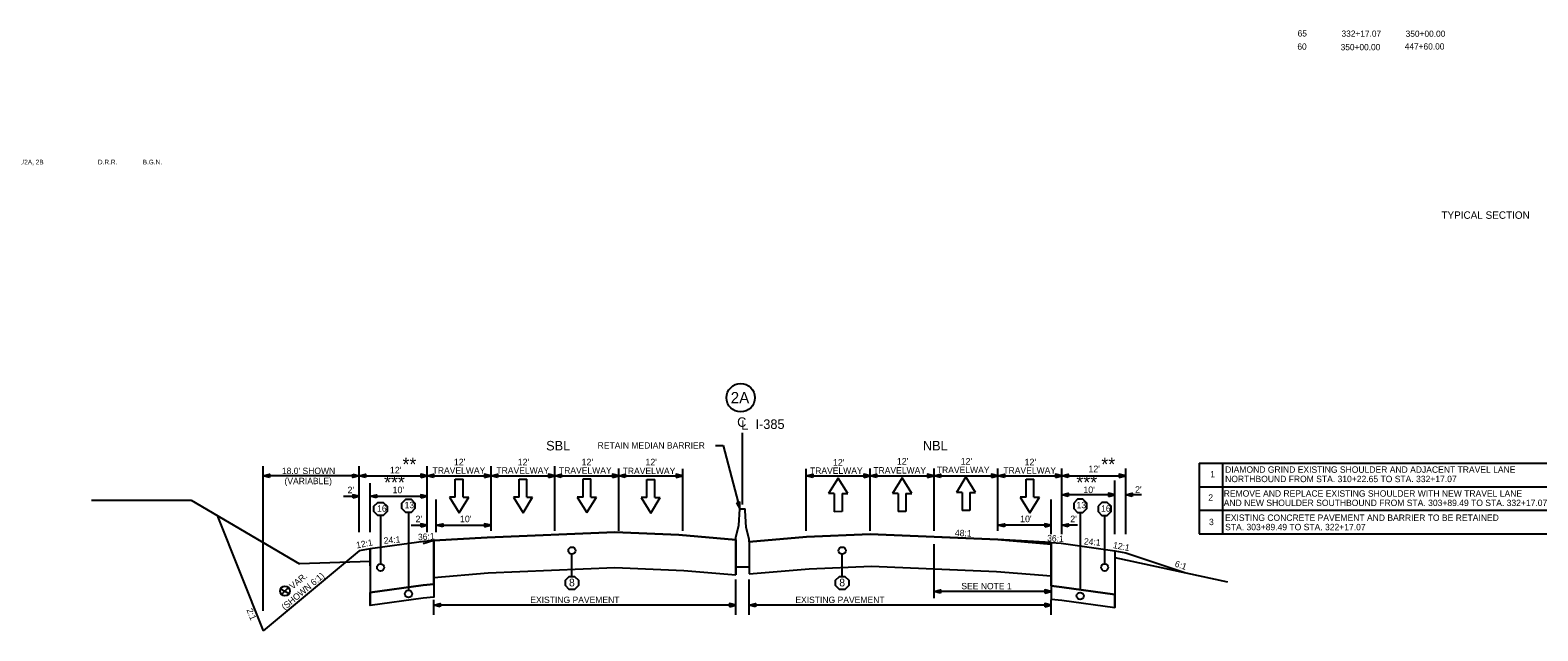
# Model space of a CAD drawing. Extents: x 4832 to 5477, y 4935 to 5220.
# Drawn here: x 5049.2 to 5332.6, y 4935 to 5047.9 of the extents above; entities that cross this region are included whole.
import ezdxf

# ---------------------------------------------------------------- set-up
doc = ezdxf.new("R2010")
doc.units = 0
for name, color, linetype in [('CLS_Clear_Zone', 7, 'Continuous'), ('Level 10', 7, 'Continuous'), ('Level 25', 7, 'Continuous'), ('Level 55', 7, 'Continuous'), ('RD_QTY_Milling', 7, 'Continuous'), ('RD_QTY_Surf_Course', 7, 'Continuous'), ('RD_SHT_TX', 7, 'Continuous'), ('RD_SHT_Typical', 7, 'Continuous'), ('RD_TX_Misc1', 7, 'Continuous'), ('RD_TX_RoadID', 7, 'Continuous'), ('RD_TX_TypSect', 7, 'Continuous'), ('RD_XS_ExPaveRet', 7, 'Continuous'), ('RD_XS_PaveShd', 7, 'Continuous'), ('TERMINATOR', 7, 'Continuous'), ('typical2', 7, 'Continuous'), ('typical_on', 7, 'Continuous')]:
    doc.layers.add(name, color=color, linetype=linetype)

# ---------------------------------------------------------------- blocks, each defined once
blk = doc.blocks.new('AH')
at = {"layer": 'TERMINATOR'}
blk.add_lwpolyline([(-6, 1.5), (0, 0), (-6, -1.5)], close=True, dxfattribs=at)

msp = doc.modelspace()

# ---------------------------------------------------------------- linework, layer by layer
at = {"layer": 'CLS_Clear_Zone'}
for p, q in [((5113.11, 4942.23), (5113.11, 4939.76)), ((5125.11, 4943.81), (5125.11, 4941.34)), ((5241.11, 4943.45), (5241.11, 4940.98)), ((5253.11, 4941.86), (5253.11, 4939.39))]:
    msp.add_line(p, q, dxfattribs=at)
at = {"layer": 'Level 10'}
for p, q in [((5219.11, 4952.68), (5231.11, 4952.18)), ((5231.11, 4952.18), (5241.11, 4951.62))]:
    msp.add_line(p, q, dxfattribs=at)
at = {"layer": 'Level 25'}
msp.add_circle((5182.77, 4978.84), 2.67, dxfattribs=at)
at = {"layer": 'Level 55'}
for p, q in [((5060.74, 4959.57), (5079.47, 4959.57)), ((5079.47, 4959.57), (5099.87, 4947.63)), ((5182.44, 4954.81), (5182.61, 4957.98)), ((5182.61, 4957.98), (5183.11, 4957.98)), ((5183.11, 4957.98), (5183.61, 4957.98)), ((5183.61, 4957.61), (5183.61, 4957.98)), ((5183.78, 4954.45), (5183.61, 4957.61)), ((5181.86, 4952.65), (5182.44, 4954.81)), ((5184.36, 4952.28), (5183.78, 4954.45)), ((5125.11, 4951.99), (5123.11, 4951.38)), ((5181.86, 4952.15), (5181.86, 4952.65)), ((5184.36, 4951.78), (5184.36, 4952.28)), ((5113.11, 4948.04), (5099.87, 4947.63)), ((5253.11, 4948.83), (5274.27, 4944.22)), ((5181.86, 4947.06), (5184.36, 4947.06))]:
    msp.add_line(p, q, dxfattribs=at)
at = {"layer": 'RD_QTY_Milling'}
for points in [[(5113.11, 4942.23), (5123.11, 4943.63), (5125.11, 4943.81), (5125.11, 4941.34), (5123.11, 4941.16), (5113.11, 4939.76)], [(5253.11, 4941.86), (5243.11, 4943.26), (5241.11, 4943.45), (5241.11, 4940.98), (5243.11, 4940.79), (5253.11, 4939.39)]]:
    msp.add_lwpolyline(points, close=True, dxfattribs=at)
at = {"layer": 'RD_SHT_Typical'}
for p, q in [((5084.36, 4956.71), (5093.04, 4935.02)), ((5125.11, 4951.99), (5123.21, 4951.84)), ((5125.11, 4951.99), (5125.11, 4943.81)), ((5241.11, 4951.62), (5243.01, 4951.48)), ((5241.11, 4951.62), (5241.11, 4943.42)), ((5111.05, 4950.03), (5093.04, 4935.02)), ((5113.11, 4948.82), (5113.11, 4950.43)), ((5113.11, 4947.21), (5113.11, 4948.82)), ((5113.11, 4947.21), (5113.11, 4942.23)), ((5123.11, 4943.63), (5113.11, 4942.23)), ((5125.11, 4943.81), (5123.11, 4943.63)), ((5241.11, 4943.45), (5243.11, 4943.26)), ((5241.11, 4943.45), (5243.11, 4943.26)), ((5243.11, 4943.26), (5253.11, 4941.86)), ((5243.11, 4943.26), (5253.11, 4941.86)), ((5123.11, 4941.16), (5113.11, 4939.76)), ((5125.11, 4941.34), (5123.11, 4941.16)), ((5241.11, 4940.98), (5243.11, 4940.79)), ((5243.11, 4940.79), (5253.11, 4939.39))]:
    msp.add_line(p, q, dxfattribs=at)
at = {"layer": 'RD_TX_Misc1'}
for p, q in [((5129.13, 4963.55), (5130.58, 4963.56)), ((5129.13, 4960.15), (5129.13, 4963.55)), ((5130.58, 4960.15), (5130.58, 4963.56)), ((5141.13, 4963.55), (5142.59, 4963.56)), ((5141.13, 4960.15), (5141.13, 4963.55)), ((5142.59, 4960.15), (5142.59, 4963.56)), ((5153.14, 4963.57), (5154.6, 4963.58)), ((5153.14, 4960.16), (5153.14, 4963.57)), ((5154.6, 4960.17), (5154.6, 4963.58)), ((5165.14, 4963.46), (5166.6, 4963.47)), ((5165.14, 4960.06), (5165.14, 4963.46)), ((5166.6, 4960.07), (5166.6, 4963.47)), ((5201.08, 4963.75), (5199.3, 4960.82)), ((5202.91, 4960.83), (5201.08, 4963.75)), ((5213.09, 4963.76), (5211.3, 4960.83)), ((5214.91, 4960.84), (5213.09, 4963.76)), ((5225.09, 4963.94), (5223.31, 4961.02)), ((5226.92, 4961.03), (5225.09, 4963.94)), ((5236.41, 4963.55), (5237.87, 4963.56)), ((5236.41, 4960.15), (5236.41, 4963.55)), ((5237.87, 4960.15), (5237.87, 4963.56)), ((5129.13, 4960.15), (5128.03, 4960.14)), ((5128.03, 4960.14), (5129.86, 4957.23)), ((5129.86, 4957.23), (5131.64, 4960.15)), ((5130.58, 4960.15), (5131.64, 4960.15)), ((5141.13, 4960.15), (5140.04, 4960.14)), ((5140.04, 4960.14), (5141.86, 4957.23)), ((5141.86, 4957.23), (5143.65, 4960.15)), ((5142.59, 4960.15), (5143.65, 4960.15)), ((5153.14, 4960.16), (5152.04, 4960.16)), ((5152.04, 4960.16), (5153.87, 4957.25)), ((5153.87, 4957.25), (5155.65, 4960.17)), ((5154.6, 4960.17), (5155.65, 4960.17)), ((5165.14, 4960.06), (5164.05, 4960.06)), ((5164.05, 4960.06), (5165.87, 4957.14)), ((5165.87, 4957.14), (5167.66, 4960.07)), ((5166.6, 4960.07), (5167.66, 4960.07)), ((5200.35, 4960.82), (5199.3, 4960.82)), ((5200.35, 4960.82), (5200.35, 4957.42)), ((5201.81, 4960.83), (5202.91, 4960.83)), ((5201.81, 4960.83), (5201.81, 4957.43)), ((5212.36, 4960.83), (5211.3, 4960.83)), ((5212.36, 4960.83), (5212.36, 4957.43)), ((5213.82, 4960.84), (5214.91, 4960.84)), ((5213.82, 4960.84), (5213.82, 4957.44)), ((5224.37, 4961.02), (5223.31, 4961.02)), ((5224.37, 4961.02), (5224.37, 4957.61)), ((5225.82, 4961.02), (5226.92, 4961.03)), ((5225.82, 4961.02), (5225.82, 4957.62)), ((5236.41, 4960.15), (5235.32, 4960.14)), ((5235.32, 4960.14), (5237.14, 4957.23)), ((5237.14, 4957.23), (5238.92, 4960.15)), ((5237.87, 4960.15), (5238.92, 4960.15)), ((5201.81, 4957.43), (5200.35, 4957.42)), ((5213.82, 4957.44), (5212.36, 4957.43)), ((5225.82, 4957.62), (5224.37, 4957.61))]:
    msp.add_line(p, q, dxfattribs=at)
at = {"layer": 'RD_TX_TypSect'}
for p, q in [((5183.11, 4958.78), (5183.11, 4972.26)), ((5178.05, 4969.89), (5179.45, 4969.89)), ((5179.45, 4969.89), (5182.61, 4957.98)), ((5093.03, 4938.75), (5093.03, 4965.98)), ((5111.05, 4953.54), (5111.05, 4965.98)), ((5123.83, 4953.54), (5123.83, 4965.98)), ((5135.84, 4953.85), (5135.84, 4965.98)), ((5147.85, 4953.85), (5147.85, 4965.98)), ((5159.85, 4953.85), (5159.85, 4965.52)), ((5171.86, 4953.85), (5171.86, 4965.47)), ((5195.1, 4953.85), (5195.1, 4965.47)), ((5207.1, 4953.85), (5207.1, 4965.52)), ((5219.11, 4953.85), (5219.11, 4965.52)), ((5231.12, 4953.85), (5231.12, 4965.52)), ((5243.12, 4953.18), (5243.12, 4965.52)), ((5255.17, 4953.18), (5255.17, 4965.52)), ((5268.91, 4966.56), (5347.56, 4966.56)), ((5268.91, 4966.56), (5268.91, 4953.25)), ((5273.35, 4966.56), (5273.35, 4953.25)), ((5111.04, 4964.15), (5093.03, 4964.15)), ((5111.05, 4964.15), (5123.83, 4964.15)), ((5113.11, 4953.54), (5113.11, 4962.8)), ((5123.83, 4964.15), (5135.84, 4964.15)), ((5135.84, 4964.15), (5147.85, 4964.15)), ((5147.85, 4964.15), (5159.85, 4964.15)), ((5159.85, 4964.15), (5171.86, 4964.15)), ((5195.1, 4964.15), (5207.1, 4964.15)), ((5207.1, 4964.15), (5219.11, 4964.15)), ((5219.11, 4964.15), (5231.12, 4964.15)), ((5231.12, 4964.15), (5243.12, 4964.15)), ((5243.12, 4964.15), (5255.13, 4964.15)), ((5253.11, 4953.18), (5253.11, 4963.26)), ((5268.91, 4962.12), (5347.56, 4962.12)), ((5108.1, 4960.31), (5111.05, 4960.31)), ((5113.11, 4960.31), (5123.83, 4960.31)), ((5125.55, 4953.54), (5125.55, 4959.69)), ((5241.11, 4953.18), (5241.11, 4959.69)), ((5253.11, 4960.6), (5243.12, 4960.6)), ((5258.12, 4960.6), (5255.17, 4960.6)), ((5115.06, 4956.71), (5115.06, 4947.59)), ((5120.31, 4957.29), (5120.31, 4942.64)), ((5246.59, 4957.29), (5246.59, 4942.64)), ((5251.16, 4956.71), (5251.16, 4947.59)), ((5268.91, 4957.69), (5347.56, 4957.69)), ((5120.86, 4954.86), (5123.83, 4954.86)), ((5125.55, 4954.86), (5135.84, 4954.86)), ((5241.11, 4954.86), (5231.12, 4954.86)), ((5246.1, 4954.86), (5243.12, 4954.86)), ((5123.21, 4951.84), (5113.11, 4950.43)), ((5125.11, 4951.99), (5123.21, 4951.84)), ((5125.11, 4943.81), (5125.11, 4951.99)), ((5219.11, 4941.14), (5219.11, 4951.29)), ((5241.11, 4951.62), (5231.11, 4952.18)), ((5231.11, 4952.18), (5241.11, 4951.34)), ((5241.11, 4943.45), (5241.11, 4951.62)), ((5241.11, 4951.62), (5243.01, 4951.48)), ((5241.11, 4951.34), (5241.11, 4951.62)), ((5243.01, 4951.48), (5253.11, 4950.06)), ((5268.91, 4953.25), (5347.56, 4953.25)), ((5113.11, 4950.43), (5113.11, 4945.65)), ((5151.04, 4945.26), (5151.04, 4949.44)), ((5201.84, 4945.26), (5201.84, 4949.44)), ((5253.11, 4950.06), (5253.11, 4945.28)), ((5113.11, 4945.65), (5113.11, 4944.04)), ((5253.11, 4945.28), (5253.11, 4943.67)), ((5096.29, 4942.9), (5097.92, 4942.07)), ((5096.48, 4941.84), (5097.74, 4943.13)), ((5113.11, 4944.04), (5113.11, 4942.23)), ((5113.11, 4942.23), (5123.11, 4943.63)), ((5123.11, 4943.63), (5125.11, 4943.81)), ((5181.86, 4938.01), (5181.86, 4944.7)), ((5184.36, 4938.01), (5184.36, 4944.7)), ((5241.11, 4942.43), (5219.11, 4942.43)), ((5243.11, 4943.26), (5241.11, 4943.45)), ((5253.11, 4941.86), (5243.11, 4943.26)), ((5253.11, 4943.67), (5253.11, 4941.86)), ((5125.11, 4938.01), (5125.11, 4940.84)), ((5181.86, 4939.83), (5125.11, 4939.83)), ((5241.11, 4939.83), (5184.36, 4939.83)), ((5241.11, 4938.01), (5241.11, 4940.84))]:
    msp.add_line(p, q, dxfattribs=at)
for centre, radius in [((5151.04, 4950.11), 0.667), ((5201.84, 4950.11), 0.667), ((5115.08, 4946.93), 0.667), ((5251.18, 4946.93), 0.667), ((5097.11, 4942.49), 0.914), ((5120.33, 4941.97), 0.667), ((5246.58, 4941.58), 0.667)]:
    msp.add_circle(centre, radius, dxfattribs=at)
at = {"layer": 'RD_XS_ExPaveRet'}
for p, q in [((5135.11, 4952.54), (5159.11, 4953.54)), ((5159.11, 4953.54), (5135.11, 4952.54)), ((5159.11, 4953.54), (5171.11, 4953.04)), ((5171.11, 4953.04), (5159.11, 4953.54)), ((5125.11, 4951.99), (5135.11, 4952.54)), ((5135.11, 4952.54), (5125.11, 4951.99)), ((5125.11, 4951.99), (5125.11, 4945.06)), ((5171.11, 4953.04), (5181.86, 4952.15)), ((5181.86, 4952.15), (5171.11, 4953.04)), ((5181.86, 4952.15), (5181.86, 4945.54)), ((5181.86, 4945.54), (5181.86, 4952.15)), ((5184.36, 4951.78), (5195.11, 4952.68)), ((5195.11, 4952.68), (5184.36, 4951.78)), ((5184.36, 4951.78), (5184.36, 4945.75)), ((5184.36, 4951.78), (5184.36, 4945.75)), ((5195.11, 4952.68), (5207.11, 4953.18)), ((5207.11, 4953.18), (5195.11, 4952.68)), ((5207.11, 4953.18), (5231.11, 4952.18)), ((5231.11, 4952.18), (5241.11, 4951.34)), ((5241.11, 4951.34), (5231.11, 4952.18)), ((5241.11, 4945.35), (5241.11, 4951.34)), ((5125.11, 4945.06), (5135.29, 4945.91)), ((5125.11, 4945.06), (5135.29, 4945.91)), ((5135.29, 4945.91), (5159.14, 4946.9)), ((5135.29, 4945.91), (5159.14, 4946.9)), ((5159.14, 4946.9), (5172.08, 4946.36)), ((5159.14, 4946.9), (5172.08, 4946.36)), ((5172.08, 4946.36), (5181.86, 4945.54)), ((5172.08, 4946.36), (5181.86, 4945.54)), ((5184.36, 4945.75), (5195.61, 4946.69)), ((5184.36, 4945.75), (5195.61, 4946.69)), ((5195.61, 4946.69), (5207.36, 4947.18)), ((5195.61, 4946.69), (5207.36, 4947.18)), ((5207.36, 4947.18), (5230.86, 4946.2)), ((5230.86, 4946.2), (5241.11, 4945.35)), ((5230.86, 4946.2), (5241.11, 4945.35))]:
    msp.add_line(p, q, dxfattribs=at)
for points in [[(5231.11, 4952.18), (5219.11, 4952.68), (5207.11, 4953.18)], [(5207.36, 4947.18), (5219.11, 4946.69), (5230.86, 4946.2)], [(5241.11, 4945.35), (5241.11, 4945.35)]]:
    msp.add_lwpolyline(points, dxfattribs=at)
at = {"layer": 'RD_XS_PaveShd'}
for p, q in [((5123.21, 4951.84), (5113.11, 4950.43)), ((5243.01, 4951.48), (5253.11, 4950.06)), ((5113.11, 4950.43), (5111.05, 4950.03)), ((5253.11, 4950.06), (5255.17, 4949.66)), ((5253.11, 4950.06), (5253.11, 4941.86)), ((5255.17, 4949.66), (5266.26, 4945.96))]:
    msp.add_line(p, q, dxfattribs=at)
at = {"layer": 'typical_on'}
for points in [[(5121.54, 4959.03), (5121.54, 4958.01), (5120.82, 4957.29), (5119.8, 4957.29), (5119.08, 4958.01), (5119.08, 4959.03), (5119.8, 4959.75), (5120.82, 4959.75)], [(5245.36, 4959.03), (5245.36, 4958.01), (5246.08, 4957.29), (5247.1, 4957.29), (5247.82, 4958.01), (5247.82, 4959.03), (5247.1, 4959.75), (5246.08, 4959.75)], [(5116.29, 4958.45), (5116.29, 4957.43), (5115.57, 4956.71), (5114.55, 4956.71), (5113.83, 4957.43), (5113.83, 4958.45), (5114.55, 4959.17), (5115.57, 4959.17)], [(5249.93, 4958.45), (5249.93, 4957.43), (5250.65, 4956.71), (5251.67, 4956.71), (5252.39, 4957.43), (5252.39, 4958.45), (5251.67, 4959.17), (5250.65, 4959.17)], [(5152.27, 4944.54), (5152.27, 4943.52), (5151.55, 4942.8), (5150.53, 4942.8), (5149.81, 4943.52), (5149.81, 4944.54), (5150.53, 4945.26), (5151.55, 4945.26)], [(5203.07, 4944.54), (5203.07, 4943.52), (5202.35, 4942.8), (5201.33, 4942.8), (5200.61, 4943.52), (5200.61, 4944.54), (5201.33, 4945.26), (5202.35, 4945.26)]]:
    msp.add_lwpolyline(points, close=True, dxfattribs=at)

# ---------------------------------------------------------------- block references
at = {"layer": 'RD_QTY_Surf_Course', "xscale": 0.20020004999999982}
for p, yscale, rotation in [((5111.05, 4964.15), 0.20020004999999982, 180), ((5123.83, 4964.15), 0.20020004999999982, 180), ((5135.84, 4964.15), 0.20020004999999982, 180), ((5147.85, 4964.15), 0.20020004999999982, 180), ((5159.85, 4964.15), 0.20020004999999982, 180), ((5195.1, 4964.15), 0.20020004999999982, 180), ((5207.1, 4964.15), 0.20020004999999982, 180), ((5219.11, 4964.15), 0.20020004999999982, 180), ((5231.12, 4964.15), 0.20020004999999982, 180), ((5243.12, 4964.15), 0.20020004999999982, 180), ((5113.11, 4960.31), 0.20020004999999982, 180), ((5182.61, 4957.98), -0.2002000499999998, -74.53660210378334), ((5243.12, 4960.6), 0.20020004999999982, 180), ((5255.17, 4960.6), 0.20020004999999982, 180), ((5125.55, 4954.86), 0.20020004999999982, 180), ((5231.12, 4954.86), 0.20020004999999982, 180), ((5243.12, 4954.86), 0.20020004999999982, 180), ((5219.11, 4942.43), 0.20020004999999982, 180), ((5125.11, 4939.83), 0.20020004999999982, 180), ((5184.36, 4939.83), 0.20020004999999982, 180)]:
    msp.add_blockref('AH', p, dxfattribs=dict(at, yscale=yscale, rotation=rotation))
at = {"layer": 'RD_QTY_Surf_Course', "xscale": 0.20020004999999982, "yscale": -0.20020004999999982}
for p in [(5123.83, 4964.15), (5135.84, 4964.15), (5147.85, 4964.15), (5159.85, 4964.15), (5171.86, 4964.15), (5207.1, 4964.15), (5219.11, 4964.15), (5231.12, 4964.15), (5243.12, 4964.15), (5255.13, 4964.15), (5111.05, 4960.31), (5123.83, 4960.31), (5253.11, 4960.6), (5123.83, 4954.86), (5135.84, 4954.86), (5241.11, 4954.86), (5241.11, 4942.43), (5181.86, 4939.83), (5241.11, 4939.83)]:
    msp.add_blockref('AH', p, dxfattribs=at)
at = {"layer": 'TERMINATOR', "xscale": 0.20009999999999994, "yscale": 0.20009999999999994}
for p, rotation in [((5093.03, 4964.15), -179.99858210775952), ((5111.04, 4964.15), 0.0014178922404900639)]:
    msp.add_blockref('AH', p, dxfattribs=dict(at, rotation=rotation))

# ---------------------------------------------------------------- texts
at = {"layer": 'Level 25'}
msp.add_text('2A', height=2.134, dxfattribs=at).set_placement((5180.89, 4977.78))
at = {"layer": 'RD_SHT_TX'}
for s, p in [('REVISED BRIDGE LIMITS 1/2A, 2B', (5032.17, 5022.7)), ('D.R.R.', (5061.95, 5022.7)), ('B.G.N.', (5070.37, 5022.7))]:
    msp.add_text(s, height=0.88, dxfattribs=at).set_placement(p)
at = {"layer": 'RD_TX_RoadID'}
msp.add_text('TYPICAL SECTION', height=1.3967, dxfattribs=at).set_placement((5314.47, 5012.47))
at = {"layer": 'RD_TX_TypSect'}
for s, height, p in [('C', 1.79, (5182.1, 4973.37)), ('L', 1.79, (5182.86, 4972.81)), ('I-385', 1.791, (5185.55, 4972.97)), ('SBL', 1.791, (5146.2, 4968.93)), ('NBL', 1.791, (5217.01, 4968.93)), ('RETAIN MEDIAN BARRIER', 1.2001, (5155.88, 4969.28)), ("12'", 1.241, (5116.84, 4964.61)), ('**', 2.5, (5119.2, 4965.08)), ("12'", 1.241, (5128.85, 4966.12)), ("12'", 1.241, (5140.85, 4966.12)), ("12'", 1.241, (5152.86, 4966.12)), ("12'", 1.241, (5164.86, 4966.12)), ("12'", 1.241, (5200.11, 4966.06)), ("12'", 1.241, (5212.12, 4966.27)), ("12'", 1.241, (5224.12, 4966.27)), ("12'", 1.241, (5236.13, 4966.12)), ("12'", 1.241, (5248.13, 4964.83)), ('**', 2.5, (5250.55, 4965.08)), ('1', 1.2, (5271.02, 4963.86)), ('DIAMOND GRIND EXISTING SHOULDER AND ADJACENT TRAVEL LANE ', 1.2, (5273.82, 4964.73)), ('(VARIABLE)', 1.2, (5097.02, 4962.59)), ("2'", 1.241, (5108.87, 4960.89)), ('***', 2.5, (5115.74, 4961.67)), ("10'", 1.241, (5117.33, 4960.89)), ('***', 2.5, (5245.86, 4961.67)), ("10'", 1.241, (5247.17, 4960.91)), ("2'", 1.241, (5256.89, 4960.95)), ('NORTHBOUND FROM STA. 310+22.65 TO STA. 332+17.07', 1.2, (5273.82, 4962.97)), ('13', 1.2, (5119.6, 4958.07)), ('13', 1.2, (5245.9, 4958.07)), ('2', 1.2, (5270.66, 4959.49)), ('AND NEW SHOULDER SOUTHBOUND FROM STA. 303+89.49 TO STA. 332+17.07', 1.2, (5273.55, 4958.48)), ('REMOVE AND REPLACE EXISTING SHOULDER WITH NEW TRAVEL LANE', 1.2, (5273.55, 4960.24)), ('16', 1.2, (5114.43, 4957.42)), ("2'", 1.241, (5121.65, 4955.44)), ("10'", 1.241, (5130, 4955.44)), ("10'", 1.241, (5235.29, 4955.44)), ("2'", 1.241, (5244.71, 4955.44)), ('16', 1.2, (5250.5, 4957.42)), ('EXISTING CONCRETE PAVEMENT AND BARRIER TO BE RETAINED', 1.2, (5273.82, 4955.69)), ('3', 1.2, (5270.79, 4954.89)), ('STA. 303+89.49 TO STA. 322+17.07', 1.2, (5273.82, 4953.93)), ('8', 1.45, (5150.5, 4943.37)), ('8', 1.45, (5201.3, 4943.37)), ('SEE NOTE 1', 1.2, (5224.24, 4942.83))]:
    msp.add_text(s, height=height, dxfattribs=at).set_placement(p)
for s, height, rotation, p in [("18.0' SHOWN", 1.2001, 0.0007, (5096.53, 4964.49)), ('TRAVELWAY', 1.2, 359.9986, (5124.86, 4964.58)), ('TRAVELWAY', 1.2, 359.9986, (5136.86, 4964.58)), ('TRAVELWAY', 1.2, 359.9986, (5148.61, 4964.58)), ('TRAVELWAY', 1.2, 359.9986, (5160.58, 4964.48)), ('TRAVELWAY', 1.2, 359.9986, (5195.79, 4964.53)), ('TRAVELWAY', 1.2, 359.9986, (5207.7, 4964.59)), ('TRAVELWAY', 1.2, 359.9986, (5219.63, 4964.67)), ('TRAVELWAY', 1.2, 359.9986, (5232.14, 4964.58)), ('48:1', 1.2, 357.6141, (5223.02, 4952.86)), ('12:1', 1.2, 11.0189, (5110.62, 4950.5)), ('24:1', 1.2, 4.7637, (5115.72, 4951.38)), ('36:1', 1.2, 3.1799, (5122.14, 4952.04)), ('36:1', 1.2, 356.8201, (5240.34, 4951.88)), ('24:1', 1.2, 355.2363, (5247.24, 4951.27)), ('12:1', 1.2, 348.9811, (5252.68, 4950.6)), ('6:1', 1.2, 341.5651, (5264.25, 4947.14)), ('(SHOWN 6:1)', 1.2001, 39.8705, (5097.07, 4938.84)), ('VAR.', 1.2, 39.8705, (5098.57, 4942.74)), ('EXISTING PAVEMENT', 1.2001, 360, (5143.22, 4940.25)), ('EXISTING PAVEMENT', 1.2001, 360, (5193.04, 4940.25)), ('2:1', 1.2, 291.8014, (5089.85, 4938.97))]:
    msp.add_text(s, height=height, rotation=rotation, dxfattribs=at).set_placement(p)
at = {"layer": 'typical2'}
for s, p in [('65', (5287.45, 5046.74)), ('332+17.07', (5295.69, 5046.69)), ('350+00.00', (5307.75, 5046.68)), ('60', (5287.4, 5044.26)), ('350+00.00', (5295.53, 5044.16)), ('447+60.00', (5307.58, 5044.29))]:
    msp.add_text(s, height=1.173, dxfattribs=at).set_placement(p)

doc.saveas('drawing.dxf')
